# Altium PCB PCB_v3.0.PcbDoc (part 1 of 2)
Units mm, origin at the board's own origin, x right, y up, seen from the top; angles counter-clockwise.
Board outline 140 x 100 mm, 2 copper layers (Top Layer, Bottom Layer); 283 components, 163 nets, 757 pads, 121 vias.
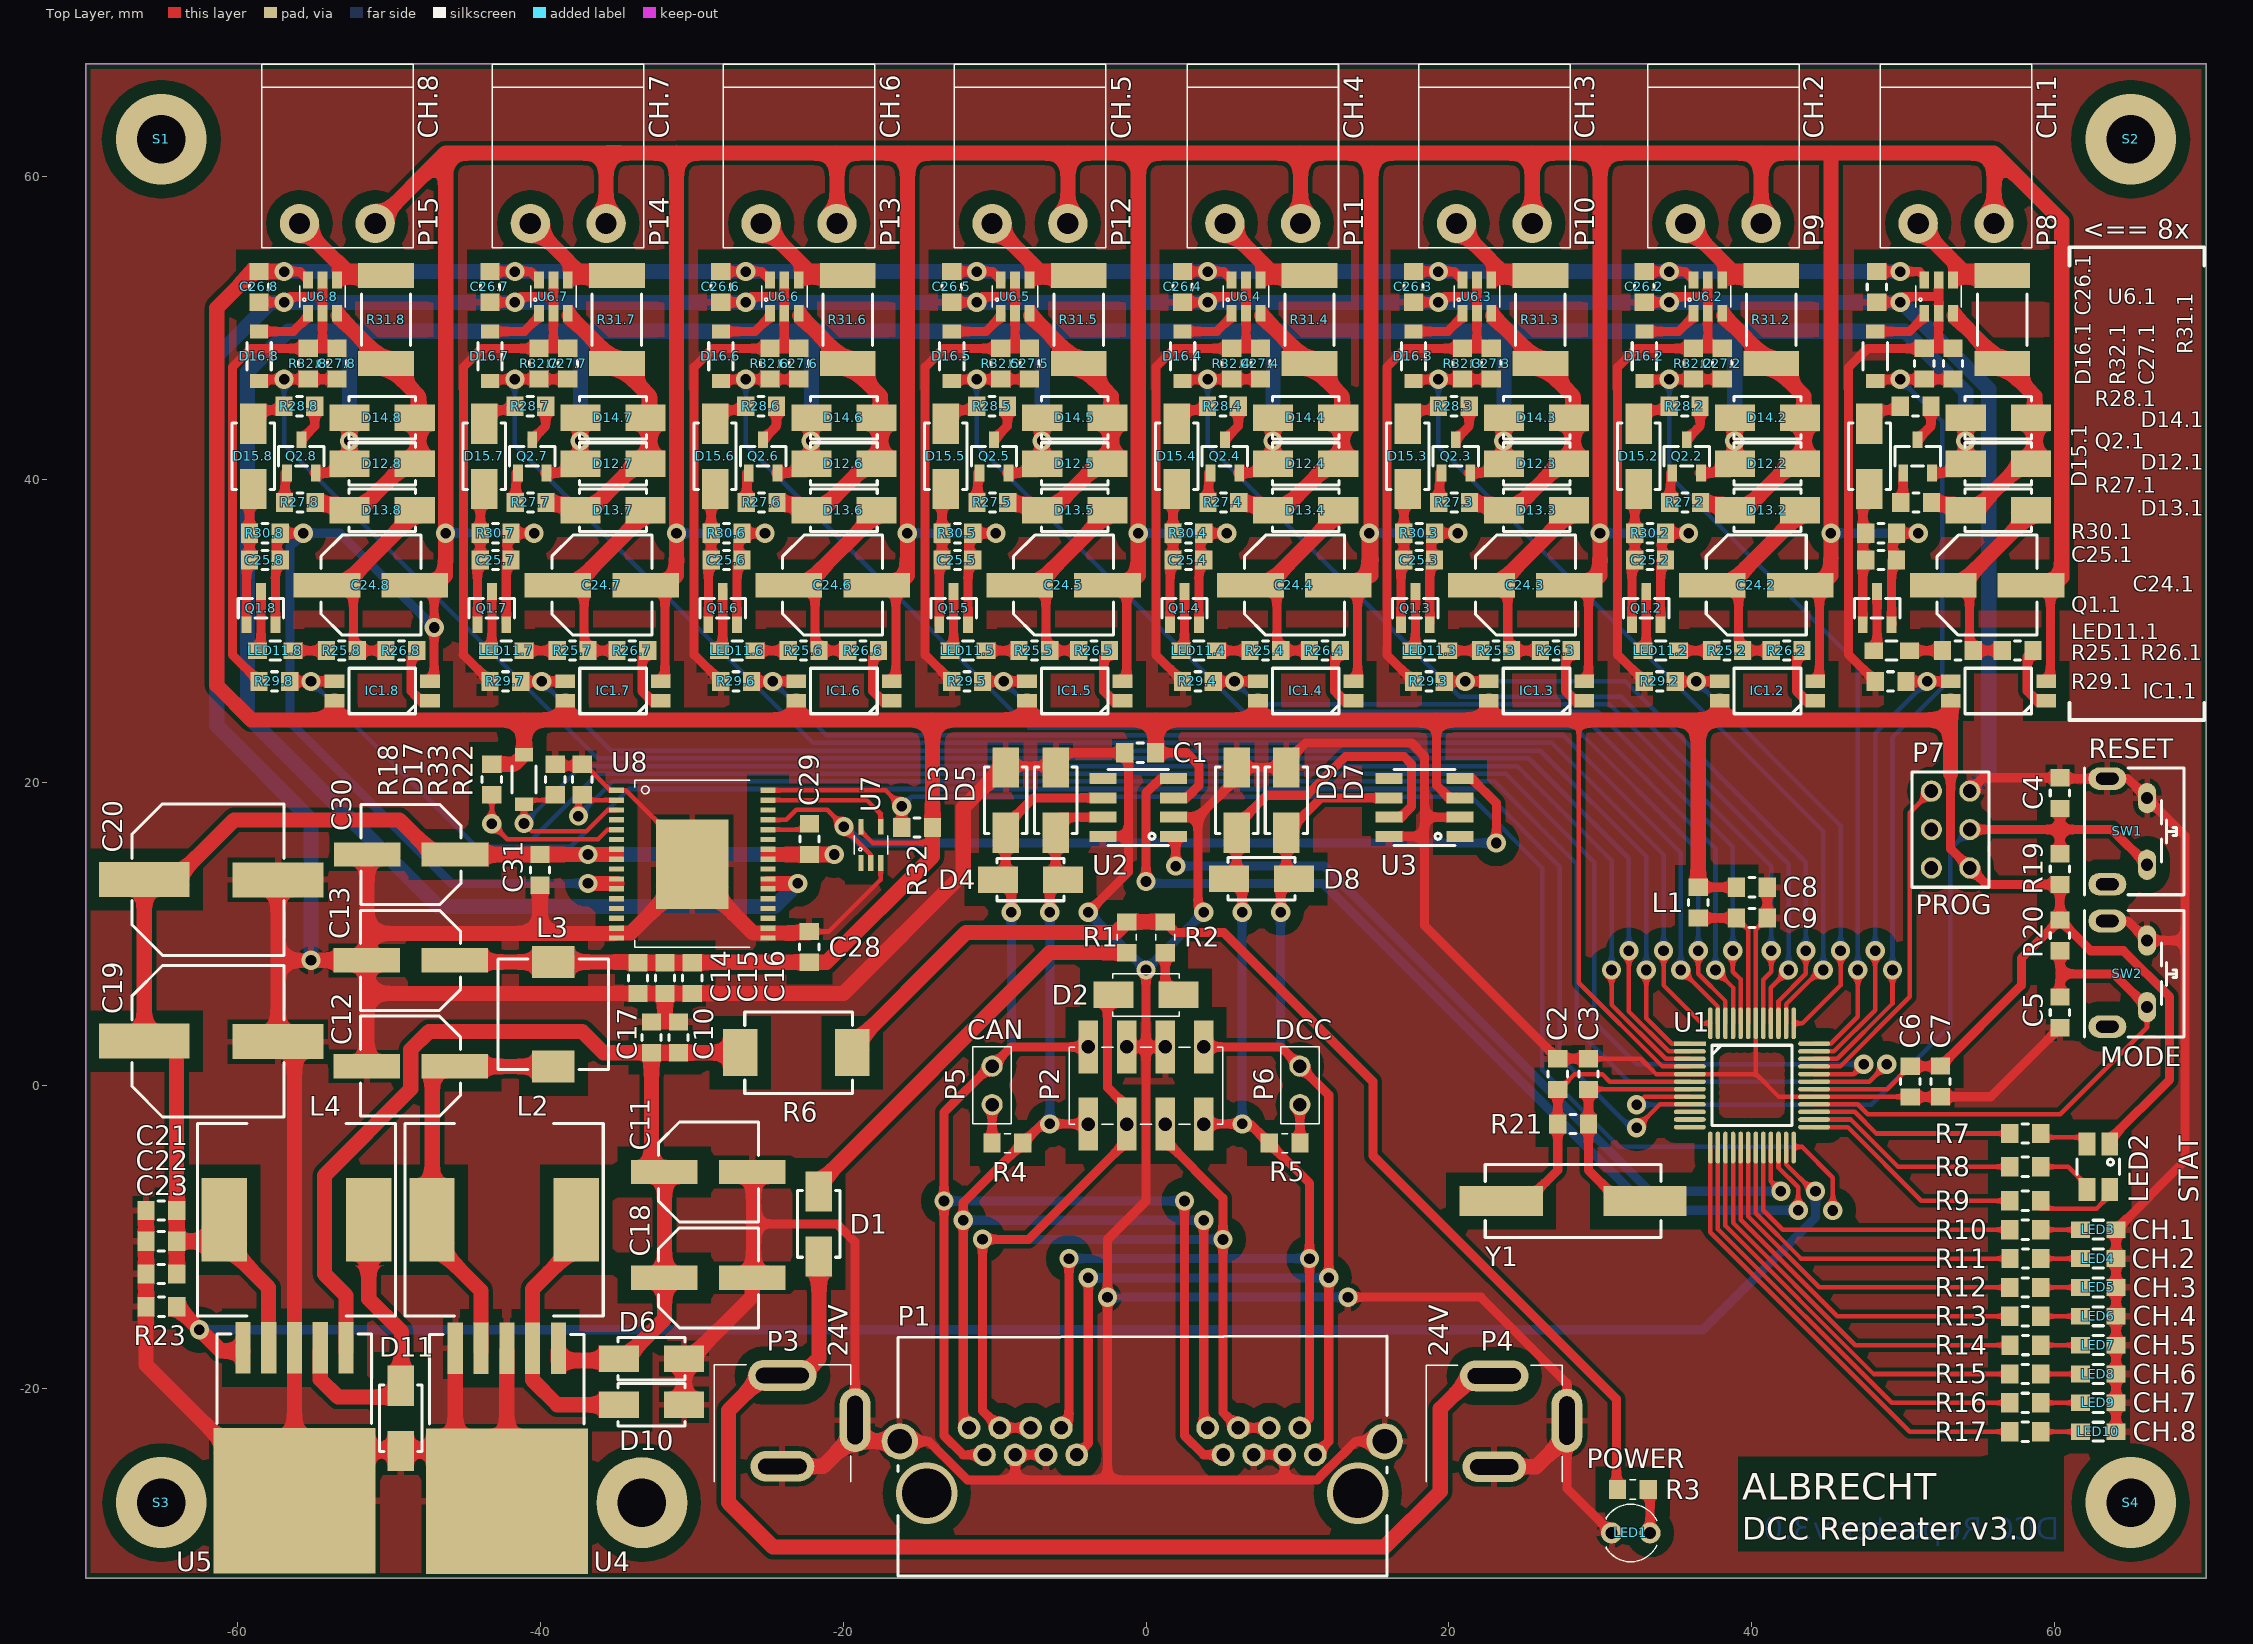
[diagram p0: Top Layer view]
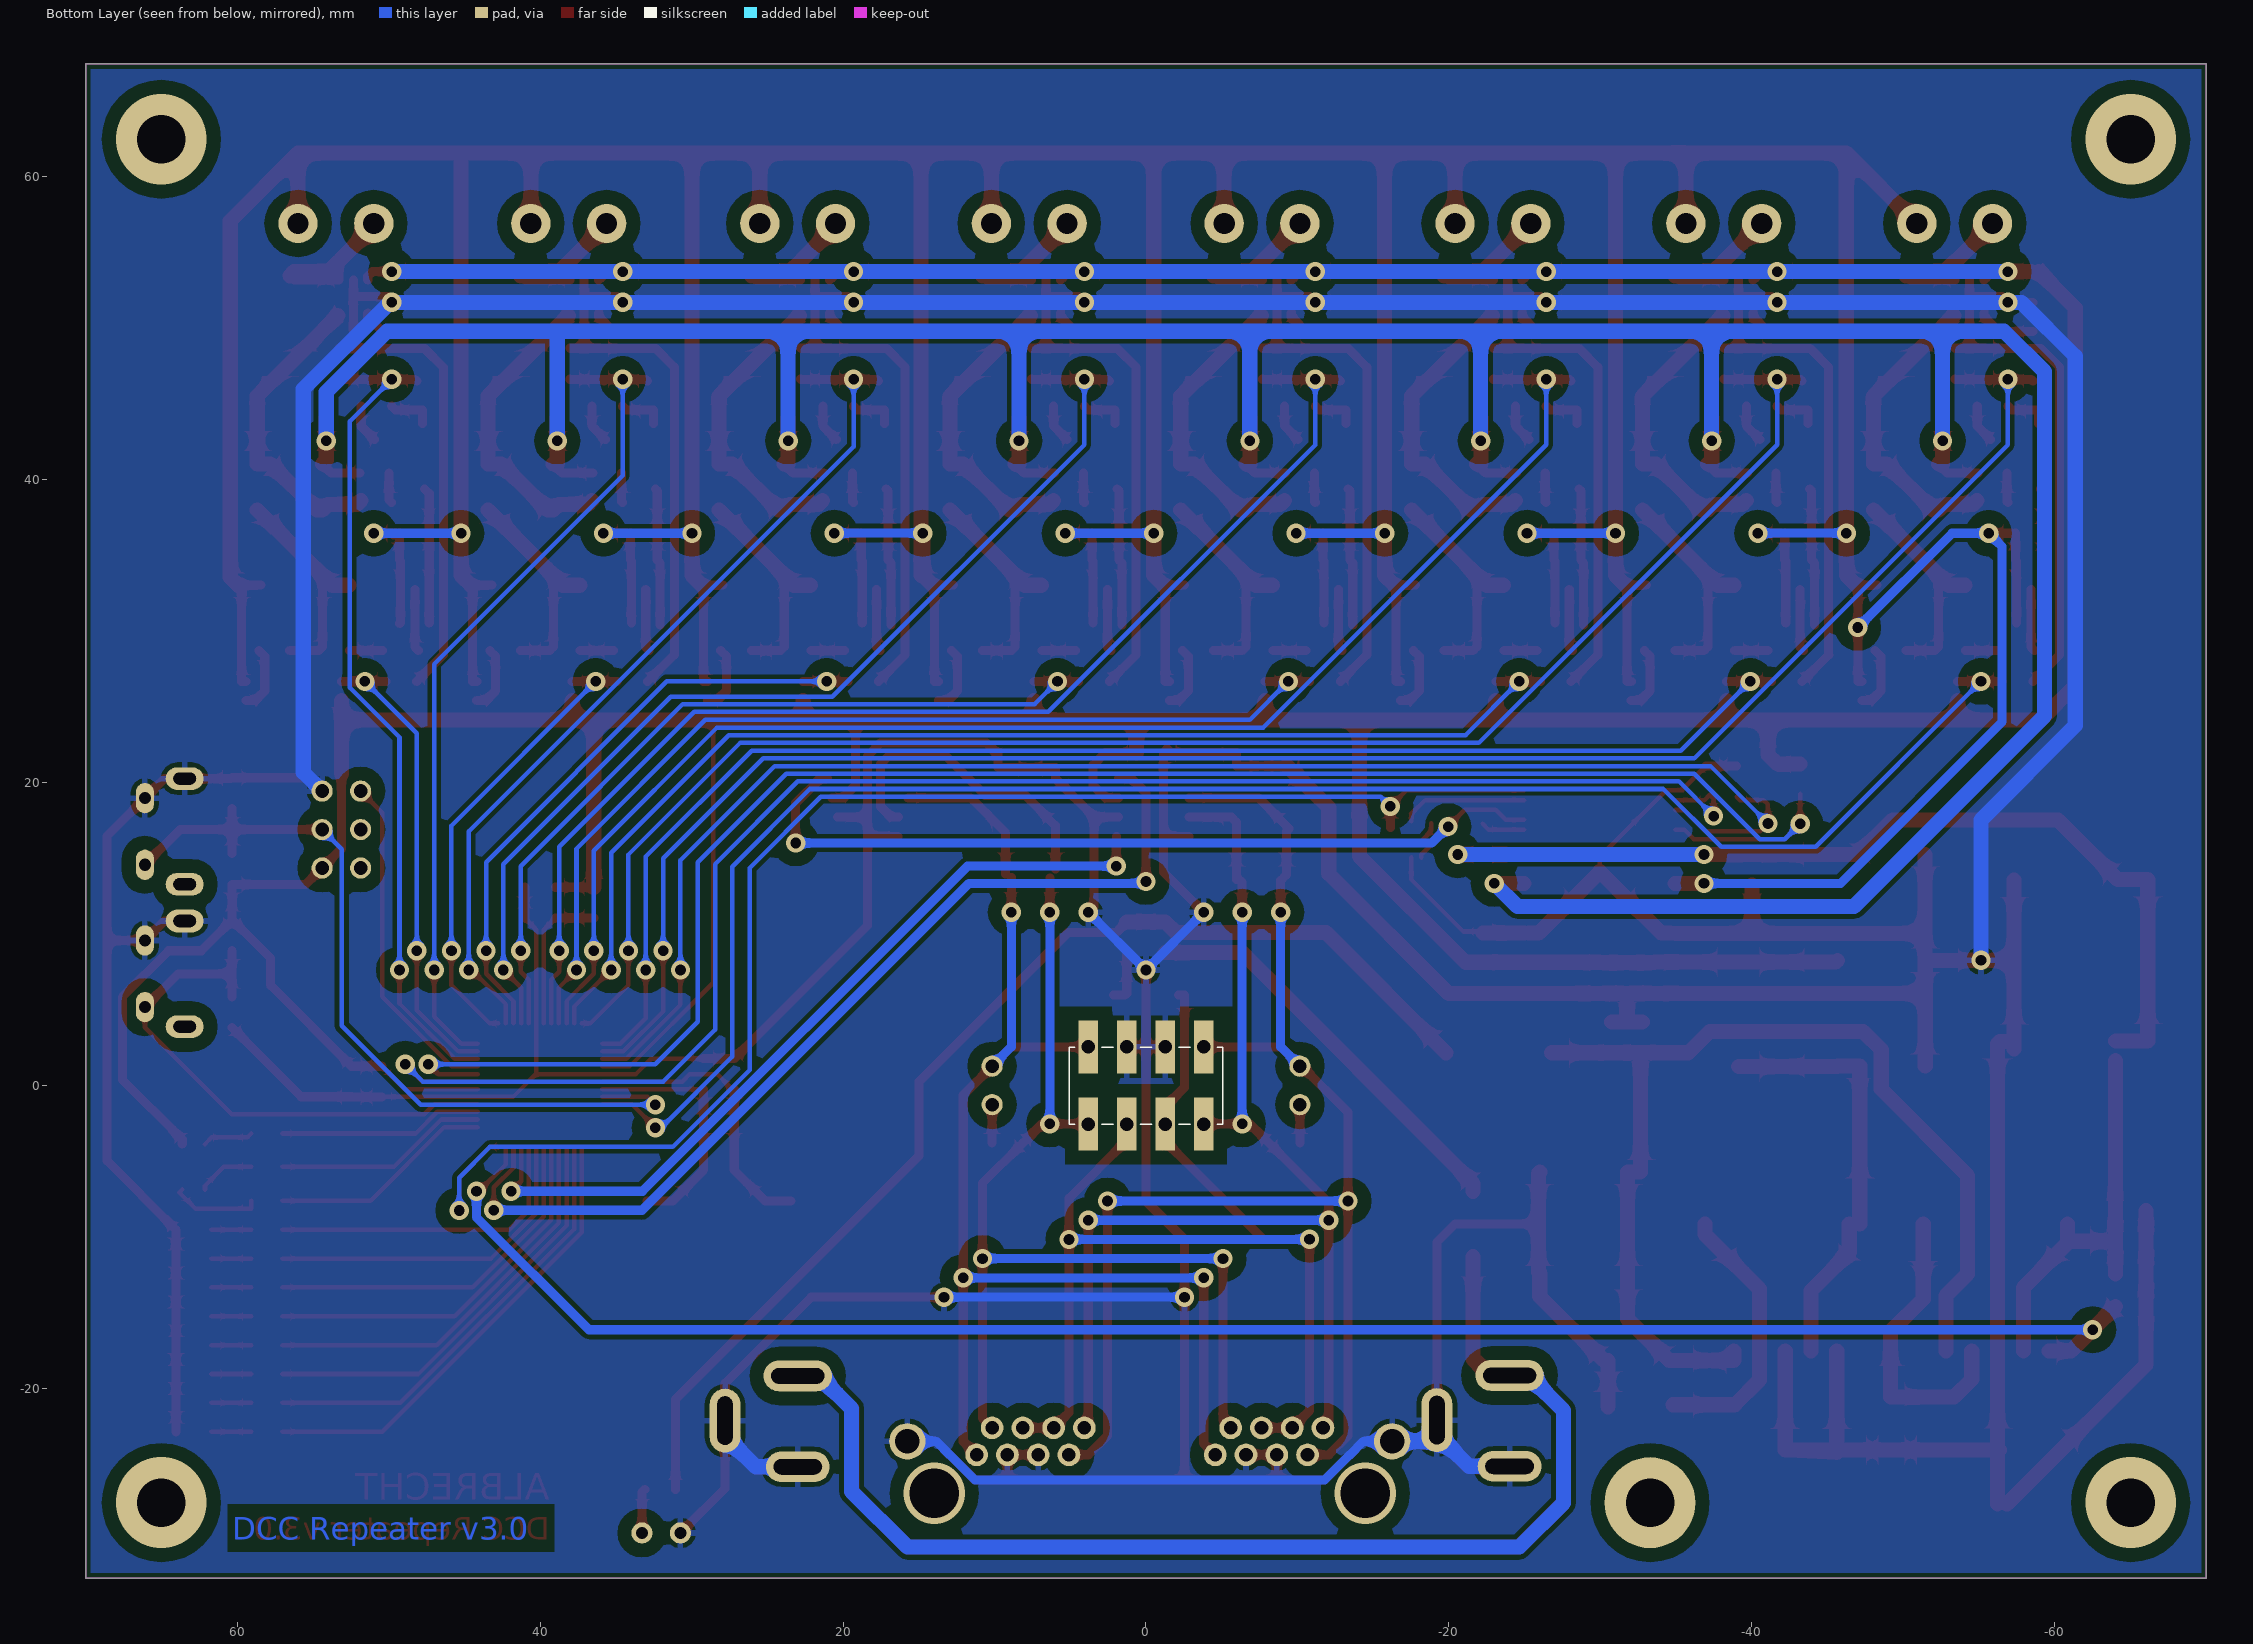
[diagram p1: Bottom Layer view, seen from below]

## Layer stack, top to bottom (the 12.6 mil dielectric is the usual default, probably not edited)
Top Solder: solder mask 0.0102, Solder Resist, Dk 3.5
Top Layer: signal copper 0.0356
Dielectric 1: dielectric 0.32, FR-4, Dk 4.8
Bottom Layer: signal copper 0.0356
Bottom Solder: solder mask 0.0102, Solder Resist, Dk 3.5

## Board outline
-70,-32.545 -70,67.455 70,67.455 70,-32.545

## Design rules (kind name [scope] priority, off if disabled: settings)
Clearance [All] p1: gap=0.2 ignorepadtopadclearanceinfootprint=FALSE except(0: Arc-Hole Track-Hole SMDPad-Hole THPad-Hole Via-Hole Fill-Hole Poly-Hole Region-Hole Text-Hole; 0.3: Arc-Poly Track-Poly Fill-Poly Poly-Poly Poly-Region Poly-Text; 0.9: SMDPad-Poly THPad-Poly Via-Poly)
Height [All] p1: minheight=0 maxheight=50 prefheight=10
HoleSize [All] p1: absolutevalues=TRUE maxlimit=3.6 minlimit=0.6 maxpercent=80.000 minpercent=20.000
MinimumSolderMaskSliver [All] p1: minsoldermaskwidth=0
PlaneConnect [All] p1: planeconnectstyle=Relief reliefexpansion=0.508 reliefentries=4 reliefconductorwidth=0.4 reliefairgap=0.3
PolygonConnect PolygonConnect_Vias [InNet('GND') and IsVia] p1: connectstyle=Relief reliefconductorwidth=0.4 reliefentries=4 polygonreliefangle="90 Angle" airgapwidth=0.3
PolygonConnect [All] p2: connectstyle=Relief reliefconductorwidth=0.4 reliefentries=4 polygonreliefangle="90 Angle" airgapwidth=0.3
RoomDefinition main_v3.0 [InComponentClass('main_v3.0')] p1: confinementstyle=ConfineIn formatcopy=TRUE lockcomponents=FALSE outline -69.977,-32.545 70.002,-32.545 70.002,67.691 -69.977,67.691
RoomDefinition U_Terminal_block [InComponentClass('U_Terminal_block')] p2: confinementstyle=ConfineIn formatcopy=TRUE lockcomponents=FALSE outline -60.96,54.61 60.96,54.61 60.96,67.455 -60.96,67.455
RoomDefinition U_Measure_current8 [InComponentClass('U_Measure_current8')] p3: confinementstyle=ConfineIn formatcopy=TRUE lockcomponents=FALSE outline -60.96,45.72 -45.72,45.72 -45.72,54.61 -60.96,54.61
RoomDefinition U_Measure_current7 [InComponentClass('U_Measure_current7')] p4: confinementstyle=ConfineIn formatcopy=TRUE lockcomponents=FALSE outline -45.72,45.72 -30.48,45.72 -30.48,54.61 -45.72,54.61
RoomDefinition U_Measure_current6 [InComponentClass('U_Measure_current6')] p5: confinementstyle=ConfineIn formatcopy=TRUE lockcomponents=FALSE outline -30.48,45.72 -15.24,45.72 -15.24,54.61 -30.48,54.61
RoomDefinition U_Measure_current5 [InComponentClass('U_Measure_current5')] p6: confinementstyle=ConfineIn formatcopy=TRUE lockcomponents=FALSE outline -15.24,45.72 0,45.72 0,54.61 -15.24,54.61
RoomDefinition U_Measure_current4 [InComponentClass('U_Measure_current4')] p7: confinementstyle=ConfineIn formatcopy=TRUE lockcomponents=FALSE outline 0,45.72 15.24,45.72 15.24,54.61 0,54.61
RoomDefinition U_Measure_current3 [InComponentClass('U_Measure_current3')] p8: confinementstyle=ConfineIn formatcopy=TRUE lockcomponents=FALSE outline 15.24,45.72 30.48,45.72 30.48,54.61 15.24,54.61
RoomDefinition U_Measure_current2 [InComponentClass('U_Measure_current2')] p9: confinementstyle=ConfineIn formatcopy=TRUE lockcomponents=FALSE outline 30.48,45.72 45.72,45.72 45.72,54.61 30.48,54.61
RoomDefinition U_Measure_current1 [InComponentClass('U_Measure_current1')] p10: confinementstyle=ConfineIn formatcopy=TRUE lockcomponents=FALSE outline 45.72,45.72 60.96,45.72 60.96,54.61 45.72,54.61
RoomDefinition U_Detect_current8 [InComponentClass('U_Detect_current8')] p11: confinementstyle=ConfineIn formatcopy=TRUE lockcomponents=FALSE outline -60.961,24.13 -45.72,24.13 -45.72,45.72 -60.961,45.72
RoomDefinition U_Detect_current7 [InComponentClass('U_Detect_current7')] p12: confinementstyle=ConfineIn formatcopy=TRUE lockcomponents=FALSE outline -45.722,24.13 -30.481,24.13 -30.481,45.72 -45.722,45.72
RoomDefinition U_Detect_current6 [InComponentClass('U_Detect_current6')] p13: confinementstyle=ConfineIn formatcopy=TRUE lockcomponents=FALSE outline -30.482,24.13 -15.241,24.13 -15.241,45.72 -30.482,45.72
RoomDefinition U_Detect_current5 [InComponentClass('U_Detect_current5')] p14: confinementstyle=ConfineIn formatcopy=TRUE lockcomponents=FALSE outline -15.241,24.13 0,24.13 0,45.72 -15.241,45.72
RoomDefinition U_Detect_current4 [InComponentClass('U_Detect_current4')] p15: confinementstyle=ConfineIn formatcopy=TRUE lockcomponents=FALSE outline 0,24.13 15.241,24.13 15.241,45.72 0,45.72
RoomDefinition U_Detect_current3 [InComponentClass('U_Detect_current3')] p16: confinementstyle=ConfineIn formatcopy=TRUE lockcomponents=FALSE outline 15.241,24.13 30.482,24.13 30.482,45.72 15.241,45.72
RoomDefinition U_Detect_current2 [InComponentClass('U_Detect_current2')] p17: confinementstyle=ConfineIn formatcopy=TRUE lockcomponents=FALSE outline 30.482,24.13 45.723,24.13 45.723,45.72 30.482,45.72
RoomDefinition U_Detect_current1 [InComponentClass('U_Detect_current1')] p18: confinementstyle=ConfineIn formatcopy=TRUE lockcomponents=FALSE outline 45.723,24.13 60.964,24.13 60.964,45.72 45.723,45.72
RoomDefinition U_DCC_Amplifier [InComponentClass('U_DCC_Amplifier')] p19: confinementstyle=ConfineIn formatcopy=TRUE lockcomponents=FALSE outline -54.482,6.985 -13.208,6.985 -13.208,22.86 -54.482,22.86
RoomDefinition U_connector [InComponentClass('U_connector')] p20: confinementstyle=ConfineIn formatcopy=TRUE lockcomponents=FALSE outline -34.29,-32.639 35,-32.639 35,12.827 -34.29,12.827
RoutingVias [All] p1: holewidth=0.7 width=1.27 viastyle="Through Hole" minholewidth=0.7 minwidth=1.27 maxholewidth=0.7 maxwidth=1.27
ShortCircuit ShortCircuit_Text [InPolygon vs IsText] p1: allowed=TRUE
ShortCircuit [All] p2: allowed=FALSE
SilkToSilkClearance [All] p1: silktosilkclearance=0.1
SilkToSolderMaskClearance [IsPad] p1: minsilkscreentomaskgap=0.1 clearancetoexposedcopper=TRUE
SolderMaskExpansion [All] p1: expansion=0.1
Width [All] p1: maxlimit=1 minlimit=0.3 preferedwidth=0.6
23 further rules are at their usual default settings.

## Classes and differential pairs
channel class measuring_v3.0: U_Measuring_1 U_Measuring_2 U_Measuring_3 U_Measuring_4 U_Measuring_5 U_Measuring_6 U_Measuring_7 U_Measuring_8
channel class measure_current_v3.0: U_Measure_current1 U_Measure_current2 U_Measure_current3 U_Measure_current4 U_Measure_current5 U_Measure_current6 U_Measure_current7 U_Measure_current8
channel class detect_current_v3.0: U_Detect_current1 U_Detect_current2 U_Detect_current3 U_Detect_current4 U_Detect_current5 U_Detect_current6 U_Detect_current7 U_Detect_current8
component class U_Terminal_block: P8 P9 P10 P11 P12 P13 P14 P15 P16
component class U_Measure_current8: C26.8 C27.8 D16.8 R31.8 R32.8 U6.8
component class U_Measure_current7: C26.7 C27.7 D16.7 R31.7 R32.7 U6.7
component class U_Measure_current6: C26.6 C27.6 D16.6 R31.6 R32.6 U6.6
component class U_Measure_current5: C26.5 C27.5 D16.5 R31.5 R32.5 U6.5
component class U_Measure_current4: C26.4 C27.4 D16.4 R31.4 R32.4 U6.4
component class U_Measure_current3: C26.3 C27.3 D16.3 R31.3 R32.3 U6.3
component class U_Measure_current2: C26.2 C27.2 D16.2 R31.2 R32.2 U6.2
component class U_Measure_current1: C26.1 C27.1 D16.1 R31.1 R32.1 U6.1
component class U_Detect_current8: C24.8 C25.8 D12.8 D13.8 D14.8 D15.8 IC1.8 LED11.8 Q1.8 Q2.8 R25.8 R26.8 R27.8 R28.8 R29.8 R30.8
component class U_Detect_current7: C24.7 C25.7 D12.7 D13.7 D14.7 D15.7 IC1.7 LED11.7 Q1.7 Q2.7 R25.7 R26.7 R27.7 R28.7 R29.7 R30.7
component class U_Detect_current6: C24.6 C25.6 D12.6 D13.6 D14.6 D15.6 IC1.6 LED11.6 Q1.6 Q2.6 R25.6 R26.6 R27.6 R28.6 R29.6 R30.6
component class U_Detect_current5: C24.5 C25.5 D12.5 D13.5 D14.5 D15.5 IC1.5 LED11.5 Q1.5 Q2.5 R25.5 R26.5 R27.5 R28.5 R29.5 R30.5
component class U_Detect_current4: C24.4 C25.4 D12.4 D13.4 D14.4 D15.4 IC1.4 LED11.4 Q1.4 Q2.4 R25.4 R26.4 R27.4 R28.4 R29.4 R30.4
component class U_Detect_current3: C24.3 C25.3 D12.3 D13.3 D14.3 D15.3 IC1.3 LED11.3 Q1.3 Q2.3 R25.3 R26.3 R27.3 R28.3 R29.3 R30.3
component class U_Detect_current2: C24.2 C25.2 D12.2 D13.2 D14.2 D15.2 IC1.2 LED11.2 Q1.2 Q2.2 R25.2 R26.2 R27.2 R28.2 R29.2 R30.2
component class U_Detect_current1: C24.1 C25.1 D12.1 D13.1 D14.1 D15.1 IC1.1 LED11.1 Q1.1 Q2.1 R25.1 R26.1 R27.1 R28.1 R29.1 R30.1
component class U_DCC_Amplifier: C28 C29 C30 C31 D17 R32 R33 R34 U7 U8
component class U_power: C10 C11 C12 C13 C14 C15 C16 C17 C18 C19 C20 C21 C22 C23 D6 D10 D11 L2 L3 L4 R6 R23 U4 U5
component class U_CAN: C1 D3 D4 D5 U2
component class U_MCU: C2 C3 C4 C5 C6 C7 C8 C9 D7 D8 D9 L1 LED2 LED3 LED4 LED5 LED6 LED7 LED8 LED9 LED10 P7 R7 R8 R9 R10 R11 R12 R13 R14 R15 R16 R17 R18 R19 R20 R21 R22 SW1 SW2 U1 U3 Y1
component class U_connector: D1 D2 LED1 P1 P2 P3 P4 P5 P6 R1 R2 R3 R4 R5
component class main_v3.0: S1 S2 S3 S4

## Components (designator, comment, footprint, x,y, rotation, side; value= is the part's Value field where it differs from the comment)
C1 "1u" SMD_CAPACITOR_0805 -0.381,21.96 r180 top
C2 "22p" SMD_CAPACITOR_0805 27.178,0.75 r270 top
C3 "22p" SMD_CAPACITOR_0805 29.21,0.75 r270 top
C4 "100n" SMD_CAPACITOR_0805 60.325,19.293 r90 top
C5 "100n" SMD_CAPACITOR_0805 60.325,4.826 r270 top
C6 "100n" SMD_CAPACITOR_0805 50.448,0.25 r270 top
C7 "100n" SMD_CAPACITOR_0805 52.451,0.265 r270 top
C8 "100n" SMD_CAPACITOR_0805 39.996,13.08 r0 top
C9 "330p" SMD_CAPACITOR_0805 39.996,11.05 r180 top
C10 "10u" SMD_CAPACITOR_0805 -30.861,3.175 r270 top value=100n
C11 "100u" SMD_CAPACITOR_D_6.3MM -28.891,-5.715 r90 top
C12 "100u" SMD_CAPACITOR_D_6.3MM -48.535,1.27 r270 top
C13 "100u" SMD_CAPACITOR_D_6.3MM -48.535,8.255 r270 top
C14 "10u" SMD_CAPACITOR_0805 -33.528,7.087 r90 top
C15 "100n" SMD_CAPACITOR_0805 -31.75,7.087 r90 top
C16 "10n" SMD_CAPACITOR_0805 -29.951,7.087 r90 top
C17 "10n" SMD_CAPACITOR_0805 -32.639,3.175 r270 top value=100n
C18 "100u" SMD_CAPACITOR_D_6.3MM -28.891,-12.7 r90 top
C19 "470u/16V" SMD_CAPACITOR_D_10MM -61.722,2.921 r90 top
C20 "470u/16V" SMD_CAPACITOR_D_10MM -61.722,13.589 r90 top
C21 "10u" SMD_CAPACITOR_0805 -65,-8.255 r0 top
C22 "100n" SMD_CAPACITOR_0805 -65,-10.287 r0 top
C23 "10n" SMD_CAPACITOR_0805 -65,-12.446 r0 top
C24.1 "10u/50V" SMD_CAPACITOR_D_6.3MM 55.523,33.02 r90 top (schematic designator C24)
C24.2 "10u/50V" SMD_CAPACITOR_D_6.3MM 40.282,33.02 r90 top (schematic designator C24)
C24.3 "10u/50V" SMD_CAPACITOR_D_6.3MM 25.041,33.02 r90 top (schematic designator C24)
C24.4 "10u/50V" SMD_CAPACITOR_D_6.3MM 9.8,33.02 r90 top (schematic designator C24)
C24.5 "10u/50V" SMD_CAPACITOR_D_6.3MM -5.441,33.02 r90 top (schematic designator C24)
C24.6 "10u/50V" SMD_CAPACITOR_D_6.3MM -20.682,33.02 r90 top (schematic designator C24)
C24.7 "10u/50V" SMD_CAPACITOR_D_6.3MM -35.922,33.02 r90 top (schematic designator C24)
C24.8 "10u/50V" SMD_CAPACITOR_D_6.3MM -51.161,33.02 r90 top (schematic designator C24)
C25.1 "100u" SMD_CAPACITOR_0805 48.518,34.68 r180 top (schematic designator C25)
C25.2 "100u" SMD_CAPACITOR_0805 33.277,34.68 r180 top (schematic designator C25)
C25.3 "100u" SMD_CAPACITOR_0805 18.036,34.68 r180 top (schematic designator C25)
C25.4 "100u" SMD_CAPACITOR_0805 2.795,34.68 r180 top (schematic designator C25)
C25.5 "100u" SMD_CAPACITOR_0805 -12.446,34.68 r180 top (schematic designator C25)
C25.6 "100u" SMD_CAPACITOR_0805 -27.687,34.68 r180 top (schematic designator C25)
C25.7 "100u" SMD_CAPACITOR_0805 -42.927,34.68 r180 top (schematic designator C25)
C25.8 "100u" SMD_CAPACITOR_0805 -58.166,34.68 r180 top (schematic designator C25)
C26.1 "100n" SMD_CAPACITOR_0805 48.244,52.705 r90 top (schematic designator C26)
C26.2 "100n" SMD_CAPACITOR_0805 32.893,52.705 r90 top (schematic designator C26)
C26.3 "100n" SMD_CAPACITOR_0805 17.653,52.705 r90 top (schematic designator C26)
C26.4 "100n" SMD_CAPACITOR_0805 2.413,52.705 r90 top (schematic designator C26)
C26.5 "100n" SMD_CAPACITOR_0805 -12.827,52.705 r90 top (schematic designator C26)
C26.6 "100n" SMD_CAPACITOR_0805 -28.067,52.705 r90 top (schematic designator C26)
C26.7 "100n" SMD_CAPACITOR_0805 -43.307,52.705 r90 top (schematic designator C26)
C26.8 "100n" SMD_CAPACITOR_0805 -58.547,52.705 r90 top (schematic designator C26)
C27.1 "1u" SMD_CAPACITOR_0805 53.274,47.646 r270 top (schematic designator C27)
C27.2 "1u" SMD_CAPACITOR_0805 38.034,47.646 r270 top (schematic designator C27)
C27.3 "1u" SMD_CAPACITOR_0805 22.794,47.646 r270 top (schematic designator C27)
C27.4 "1u" SMD_CAPACITOR_0805 7.554,47.646 r270 top (schematic designator C27)
C27.5 "1u" SMD_CAPACITOR_0805 -7.686,47.646 r270 top (schematic designator C27)
C27.6 "1u" SMD_CAPACITOR_0805 -22.926,47.646 r270 top (schematic designator C27)
C27.7 "1u" SMD_CAPACITOR_0805 -38.166,47.646 r270 top (schematic designator C27)
C27.8 "1u" SMD_CAPACITOR_0805 -53.406,47.646 r270 top (schematic designator C27)
C28 "100n" SMD_CAPACITOR_0805 -22.225,9.144 r270 top
C29 "100n" SMD_CAPACITOR_0805 -22.218,16.256 r90 top
C30 "100u" SMD_CAPACITOR_D_6.3MM -48.514,15.24 r270 top
C31 "100n" SMD_CAPACITOR_0805 -40.005,14.224 r90 top
D1 "B340A-E3/61T" SMD_DO-214AC -21.59,-9.144 r90 top
D2 "B340A-E3/61T" SMD_DO-214AC -0.002,5.969 r0 top
D3 "SMA6J5.0CA" SMD_DO-214AC -9.271,18.83 r90 top
D4 "SMA6J5.0CA" SMD_DO-214AC -7.622,13.589 r180 top
D5 "SMA6J5.0CA" SMD_DO-214AC -5.969,18.83 r270 top
D6 "SMA6J28CA" SMD_DO-214AC -32.641,-18.034 r180 top
D7 "SMA6J5.0CA" SMD_DO-214AC 9.271,18.83 r90 top
D8 "SMA6J5.0CA" SMD_DO-214AC 7.62,13.63 r0 top
D9 "SMA6J5.0CA" SMD_DO-214AC 5.978,18.83 r270 top
D10 "B340A-E3/61T" SMD_DO-214AC -32.639,-21.082 r180 top
D11 "B340A-E3/61T" SMD_DO-214AC -49.2,-21.971 r90 top
D12.1 "S1A+" SMD_DO-214AC 56.265,41.021 r180 top (schematic designator D12)
D12.2 "S1A+" SMD_DO-214AC 41.024,41.021 r180 top (schematic designator D12)
D12.3 "S1A+" SMD_DO-214AC 25.783,41.021 r180 top (schematic designator D12)
D12.4 "S1A+" SMD_DO-214AC 10.542,41.021 r180 top (schematic designator D12)
D12.5 "S1A+" SMD_DO-214AC -4.699,41.021 r180 top (schematic designator D12)
D12.6 "S1A+" SMD_DO-214AC -19.94,41.021 r180 top (schematic designator D12)
D12.7 "S1A+" SMD_DO-214AC -35.18,41.021 r180 top (schematic designator D12)
D12.8 "S1A+" SMD_DO-214AC -50.419,41.021 r180 top (schematic designator D12)
D13.1 "S1A+" SMD_DO-214AC 56.265,37.973 r0 top (schematic designator D13)
D13.2 "S1A+" SMD_DO-214AC 41.024,37.973 r0 top (schematic designator D13)
D13.3 "S1A+" SMD_DO-214AC 25.783,37.973 r0 top (schematic designator D13)
D13.4 "S1A+" SMD_DO-214AC 10.542,37.973 r0 top (schematic designator D13)
D13.5 "S1A+" SMD_DO-214AC -4.699,37.973 r0 top (schematic designator D13)
D13.6 "S1A+" SMD_DO-214AC -19.94,37.973 r0 top (schematic designator D13)
D13.7 "S1A+" SMD_DO-214AC -35.18,37.973 r0 top (schematic designator D13)
D13.8 "S1A+" SMD_DO-214AC -50.419,37.973 r0 top (schematic designator D13)
D14.1 "S1A+" SMD_DO-214AC 56.265,44.069 r0 top (schematic designator D14)
D14.2 "S1A+" SMD_DO-214AC 41.024,44.069 r0 top (schematic designator D14)
D14.3 "S1A+" SMD_DO-214AC 25.783,44.069 r0 top (schematic designator D14)
D14.4 "S1A+" SMD_DO-214AC 10.542,44.069 r0 top (schematic designator D14)
D14.5 "S1A+" SMD_DO-214AC -4.699,44.069 r0 top (schematic designator D14)
D14.6 "S1A+" SMD_DO-214AC -19.94,44.069 r0 top (schematic designator D14)
D14.7 "S1A+" SMD_DO-214AC -35.18,44.069 r0 top (schematic designator D14)
D14.8 "S1A+" SMD_DO-214AC -50.419,44.069 r0 top (schematic designator D14)
D15.1 "S1A+" SMD_DO-214AC 47.756,41.529 r270 top (schematic designator D15)
D15.2 "S1A+" SMD_DO-214AC 32.515,41.529 r270 top (schematic designator D15)
D15.3 "S1A+" SMD_DO-214AC 17.274,41.529 r270 top (schematic designator D15)
D15.4 "S1A+" SMD_DO-214AC 2.033,41.529 r270 top (schematic designator D15)
D15.5 "S1A+" SMD_DO-214AC -13.208,41.529 r270 top (schematic designator D15)
D15.6 "S1A+" SMD_DO-214AC -28.449,41.529 r270 top (schematic designator D15)
D15.7 "S1A+" SMD_DO-214AC -43.689,41.529 r270 top (schematic designator D15)
D15.8 "S1A+" SMD_DO-214AC -58.928,41.529 r270 top (schematic designator D15)
D16.1 "BAT46W-7-F" SMD_SOD-123 48.133,48.133 r270 top (schematic designator D16)
D16.2 "BAT46W-7-F" SMD_SOD-123 32.897,48.133 r270 top (schematic designator D16)
D16.3 "BAT46W-7-F" SMD_SOD-123 17.657,48.133 r270 top (schematic designator D16)
D16.4 "BAT46W-7-F" SMD_SOD-123 2.417,48.133 r270 top (schematic designator D16)
D16.5 "BAT46W-7-F" SMD_SOD-123 -12.823,48.133 r270 top (schematic designator D16)
D16.6 "BAT46W-7-F" SMD_SOD-123 -28.063,48.133 r270 top (schematic designator D16)
D16.7 "BAT46W-7-F" SMD_SOD-123 -43.303,48.133 r270 top (schematic designator D16)
D16.8 "BAT46W-7-F" SMD_SOD-123 -58.543,48.133 r270 top (schematic designator D16)
D17 "BAT46W-7-F" SMD_SOD-123 -41.056,20.193 r90 top
IC1.1 "TCMT1109" TCMT110x 56.265,26.035 r180 top (schematic designator IC1)
IC1.2 "TCMT1109" TCMT110x 41.024,26.035 r180 top (schematic designator IC1)
IC1.3 "TCMT1109" TCMT110x 25.783,26.035 r180 top (schematic designator IC1)
IC1.4 "TCMT1109" TCMT110x 10.542,26.035 r180 top (schematic designator IC1)
IC1.5 "TCMT1109" TCMT110x -4.699,26.035 r180 top (schematic designator IC1)
IC1.6 "TCMT1109" TCMT110x -19.94,26.035 r180 top (schematic designator IC1)
IC1.7 "TCMT1109" TCMT110x -35.18,26.035 r180 top (schematic designator IC1)
IC1.8 "TCMT1109" TCMT110x -50.419,26.035 r180 top (schematic designator IC1)
L1 "BLM21A102SPT" SMD_INDUCTOR_0805 36.449,12.065 r270 top
L2 "330u" SMD_INDUCTOR_12.5MM -42.367,-8.865 r270 top
L3 "20u" SMD_INDUCTOR_7.3MM -39.116,4.699 r90 top
L4 "100u" SMD_INDUCTOR_12.5MM -56.07,-8.865 r270 top
LED1 "Green" THT_LED_3MM 32,-29.545 r180 top
LED2 "ASMB-MTB0-0A3A2" SMD_LED_RGB 62.865,-5.37 r180 top
LED3 "Yellow" SMD_LED_0805 62.865,-9.525 r0 top
LED4 "Yellow" SMD_LED_0805 62.865,-11.43 r0 top
LED5 "Yellow" SMD_LED_0805 62.865,-13.335 r0 top
LED6 "Yellow" SMD_LED_0805 62.865,-15.24 r0 top
LED7 "Yellow" SMD_LED_0805 62.865,-17.145 r0 top
LED8 "Yellow" SMD_LED_0805 62.865,-19.05 r0 top
LED9 "Yellow" SMD_LED_0805 62.865,-20.955 r0 top
LED10 "Yellow" SMD_LED_0805 62.865,-22.86 r0 top
LED11.1 "Red" SMD_LED_0805 49.214,28.702 r180 top (schematic designator LED11)
LED11.2 "Red" SMD_LED_0805 33.973,28.702 r180 top (schematic designator LED11)
LED11.3 "Red" SMD_LED_0805 18.732,28.702 r180 top (schematic designator LED11)
LED11.4 "Red" SMD_LED_0805 3.491,28.702 r180 top (schematic designator LED11)
LED11.5 "Red" SMD_LED_0805 -11.75,28.702 r180 top (schematic designator LED11)
LED11.6 "Red" SMD_LED_0805 -26.991,28.702 r180 top (schematic designator LED11)
LED11.7 "Red" SMD_LED_0805 -42.231,28.702 r180 top (schematic designator LED11)
LED11.8 "Red" SMD_LED_0805 -57.47,28.702 r180 top (schematic designator LED11)
P1 "RJ45 2PORT" THT_RJ45_2PORT -16.377,-32.384 r0 top locked
P2 "Header 2x4" SMD_HEADER_100MIL_2X4_DOUBLESIDED 0,-0.01 r90 top locked
P3 "Power JACK 2.1/2.5" THT_POWER_JACK_2.1/2.5 -21.603,-22.146 r270 top locked
P4 "Power JACK 2.1/2.5" THT_POWER_JACK_2.1/2.5 25.387,-22.177 r270 top locked
P5 "Header 1x2" THT_HEADER_100MIL_1X2_MALE -10.16,0 r180 top locked
P6 "Header 1x2" THT_HEADER_100MIL_1X2_MALE 10.16,0 r180 top locked
P7 "Programming connector" THT_HEADER_100MIL_2X3_MALE 53.115,16.891 r180 top
P8 "End_Terminal_2pos_5.00mm" Terminal_Block_2pos_5.00mm_pitch 50.974,56.896 r0 top locked
P9 "End_Terminal_2pos_5.00mm" Terminal_Block_2pos_5.00mm_pitch 35.607,56.896 r0 top locked
P10 "End_Terminal_2pos_5.00mm" Terminal_Block_2pos_5.00mm_pitch 20.494,56.896 r0 top locked
P11 "End_Terminal_2pos_5.00mm" Terminal_Block_2pos_5.00mm_pitch 5.207,56.896 r0 top locked
P12 "End_Terminal_2pos_5.00mm" Terminal_Block_2pos_5.00mm_pitch -10.16,56.896 r0 top locked
P13 "End_Terminal_2pos_5.00mm" Terminal_Block_2pos_5.00mm_pitch -25.4,56.896 r0 top locked
P14 "End_Terminal_2pos_5.00mm" Terminal_Block_2pos_5.00mm_pitch -40.64,56.896 r0 top locked
P15 "End_Terminal_2pos_5.00mm" Terminal_Block_2pos_5.00mm_pitch -55.88,56.896 r0 top locked
Q1.1 "IRLML2030TRPBF" SMD_SOT-23 48.264,31.5 r0 top (schematic designator Q1)
Q1.2 "IRLML2030TRPBF" SMD_SOT-23 33.023,31.5 r0 top (schematic designator Q1)
Q1.3 "IRLML2030TRPBF" SMD_SOT-23 17.782,31.5 r0 top (schematic designator Q1)
Q1.4 "IRLML2030TRPBF" SMD_SOT-23 2.541,31.5 r0 top (schematic designator Q1)
Q1.5 "IRLML2030TRPBF" SMD_SOT-23 -12.7,31.5 r0 top (schematic designator Q1)
Q1.6 "IRLML2030TRPBF" SMD_SOT-23 -27.941,31.5 r0 top (schematic designator Q1)
Q1.7 "IRLML2030TRPBF" SMD_SOT-23 -43.181,31.5 r0 top (schematic designator Q1)
Q1.8 "IRLML2030TRPBF" SMD_SOT-23 -58.42,31.5 r0 top (schematic designator Q1)
Q2.1 "BC807" SMD_SOT-23 50.931,41.529 r0 top (schematic designator Q2)
Q2.2 "BC807" SMD_SOT-23 35.69,41.529 r0 top (schematic designator Q2)
Q2.3 "BC807" SMD_SOT-23 20.449,41.529 r0 top (schematic designator Q2)
Q2.4 "BC807" SMD_SOT-23 5.208,41.529 r0 top (schematic designator Q2)
Q2.5 "BC807" SMD_SOT-23 -10.033,41.529 r0 top (schematic designator Q2)
Q2.6 "BC807" SMD_SOT-23 -25.274,41.529 r0 top (schematic designator Q2)
Q2.7 "BC807" SMD_SOT-23 -40.514,41.529 r0 top (schematic designator Q2)
Q2.8 "BC807" SMD_SOT-23 -55.753,41.529 r0 top (schematic designator Q2)
R1 "0" SMD_RESISTOR_0805 -1.27,9.779 r270 top
R2 "0" SMD_RESISTOR_0805 1.27,9.779 r270 top
R3 "2k2" SMD_RESISTOR_0805 32.131,-26.67 r180 top
R4 "120" SMD_RESISTOR_0805 -9.144,-3.81 r0 top
R5 "120" SMD_RESISTOR_0805 9.148,-3.81 r180 top
R6 "MF-SM300-2" SMD_RESISTOR_PTC_MF-SM -23.086,2.16 r180 top
R7 "290" SMD_RESISTOR_0805 58.039,-3.175 r180 top
R8 "190" SMD_RESISTOR_0805 58.039,-5.37 r180 top
R9 "190" SMD_RESISTOR_0805 58.039,-7.62 r180 top
R10 "560" SMD_RESISTOR_0805 58.039,-9.525 r0 top
R11 "560" SMD_RESISTOR_0805 58.044,-11.43 r0 top
R12 "560" SMD_RESISTOR_0805 58.039,-13.335 r0 top
R13 "560" SMD_RESISTOR_0805 58.039,-15.24 r0 top
R14 "560" SMD_RESISTOR_0805 58.044,-17.145 r0 top
R15 "560" SMD_RESISTOR_0805 58.039,-19.05 r0 top
R16 "560" SMD_RESISTOR_0805 58.039,-20.955 r0 top
R17 "560" SMD_RESISTOR_0805 58.039,-22.86 r0 top
R18 "10k" SMD_RESISTOR_0805 -43.181,20.193 r90 top
R19 "10k" SMD_RESISTOR_0805 60.325,14.28 r270 top
R20 "10k" SMD_RESISTOR_0805 60.325,9.906 r90 top
R21 "1M" SMD_RESISTOR_0805 28.194,-2.54 r180 top
R22 "10k" SMD_RESISTOR_0805 -37.211,20.193 r270 top
R23 "10k" SMD_RESISTOR_0805 -65,-14.605 r0 top
R25.1 "560" SMD_RESISTOR_0805 53.598,28.702 r0 top (schematic designator R25)
R25.2 "560" SMD_RESISTOR_0805 38.357,28.702 r0 top (schematic designator R25)
R25.3 "560" SMD_RESISTOR_0805 23.116,28.702 r0 top (schematic designator R25)
R25.4 "560" SMD_RESISTOR_0805 7.875,28.702 r0 top (schematic designator R25)
R25.5 "560" SMD_RESISTOR_0805 -7.366,28.702 r0 top (schematic designator R25)
R25.6 "560" SMD_RESISTOR_0805 -22.607,28.702 r0 top (schematic designator R25)
R25.7 "560" SMD_RESISTOR_0805 -37.847,28.702 r0 top (schematic designator R25)
R25.8 "560" SMD_RESISTOR_0805 -53.086,28.702 r0 top (schematic designator R25)
R26.1 "330" SMD_RESISTOR_0805 57.535,28.702 r0 top (schematic designator R26)
R26.2 "330" SMD_RESISTOR_0805 42.294,28.702 r0 top (schematic designator R26)
R26.3 "330" SMD_RESISTOR_0805 27.053,28.702 r0 top (schematic designator R26)
R26.4 "330" SMD_RESISTOR_0805 11.812,28.702 r0 top (schematic designator R26)
R26.5 "330" SMD_RESISTOR_0805 -3.429,28.702 r0 top (schematic designator R26)
R26.6 "330" SMD_RESISTOR_0805 -18.67,28.702 r0 top (schematic designator R26)
R26.7 "330" SMD_RESISTOR_0805 -33.91,28.702 r0 top (schematic designator R26)
R26.8 "330" SMD_RESISTOR_0805 -49.149,28.702 r0 top (schematic designator R26)
R27.1 "1k" SMD_RESISTOR_0805 50.828,38.481 r0 top (schematic designator R27)
R27.2 "1k" SMD_RESISTOR_0805 35.587,38.481 r0 top (schematic designator R27)
R27.3 "1k" SMD_RESISTOR_0805 20.346,38.481 r0 top (schematic designator R27)
R27.4 "1k" SMD_RESISTOR_0805 5.105,38.481 r0 top (schematic designator R27)
R27.5 "1k" SMD_RESISTOR_0805 -10.136,38.481 r0 top (schematic designator R27)
R27.6 "1k" SMD_RESISTOR_0805 -25.377,38.481 r0 top (schematic designator R27)
R27.7 "1k" SMD_RESISTOR_0805 -40.617,38.481 r0 top (schematic designator R27)
R27.8 "1k" SMD_RESISTOR_0805 -55.856,38.481 r0 top (schematic designator R27)
R28.1 "1k" SMD_RESISTOR_0805 50.8,44.831 r0 top (schematic designator R28)
R28.2 "1k" SMD_RESISTOR_0805 35.56,44.831 r0 top (schematic designator R28)
R28.3 "1k" SMD_RESISTOR_0805 20.319,44.831 r0 top (schematic designator R28)
R28.4 "1k" SMD_RESISTOR_0805 5.078,44.831 r0 top (schematic designator R28)
R28.5 "1k" SMD_RESISTOR_0805 -10.163,44.831 r0 top (schematic designator R28)
R28.6 "1k" SMD_RESISTOR_0805 -25.404,44.831 r0 top (schematic designator R28)
R28.7 "1k" SMD_RESISTOR_0805 -40.644,44.831 r0 top (schematic designator R28)
R28.8 "1k" SMD_RESISTOR_0805 -55.883,44.831 r0 top (schematic designator R28)
R29.1 "10k" SMD_RESISTOR_0805 49.153,26.67 r0 top (schematic designator R29)
R29.2 "10k" SMD_RESISTOR_0805 33.912,26.67 r0 top (schematic designator R29)
R29.3 "10k" SMD_RESISTOR_0805 18.671,26.67 r0 top (schematic designator R29)
R29.4 "10k" SMD_RESISTOR_0805 3.43,26.67 r0 top (schematic designator R29)
R29.5 "10k" SMD_RESISTOR_0805 -11.811,26.67 r0 top (schematic designator R29)
R29.6 "10k" SMD_RESISTOR_0805 -27.052,26.67 r0 top (schematic designator R29)
R29.7 "10k" SMD_RESISTOR_0805 -42.292,26.67 r0 top (schematic designator R29)
R29.8 "10k" SMD_RESISTOR_0805 -57.531,26.67 r0 top (schematic designator R29)
R30.1 "1M" SMD_RESISTOR_0805 48.518,36.449 r180 top (schematic designator R30)
R30.2 "1M" SMD_RESISTOR_0805 33.277,36.449 r180 top (schematic designator R30)
R30.3 "1M" SMD_RESISTOR_0805 18.036,36.449 r180 top (schematic designator R30)
R30.4 "1M" SMD_RESISTOR_0805 2.795,36.449 r180 top (schematic designator R30)
R30.5 "1M" SMD_RESISTOR_0805 -12.446,36.449 r180 top (schematic designator R30)
R30.6 "1M" SMD_RESISTOR_0805 -27.687,36.449 r180 top (schematic designator R30)
R30.7 "1M" SMD_RESISTOR_0805 -42.927,36.449 r180 top (schematic designator R30)
R30.8 "1M" SMD_RESISTOR_0805 -58.166,36.449 r180 top (schematic designator R30)
R31.1 "100m" Resistor 56.515,50.546 r90 top (schematic designator R31)
R31.2 "100m" Resistor 41.275,50.546 r90 top (schematic designator R31)
R31.3 "100m" Resistor 26.035,50.546 r90 top (schematic designator R31)
R31.4 "100m" Resistor 10.795,50.546 r90 top (schematic designator R31)
R31.5 "100m" Resistor -4.445,50.546 r90 top (schematic designator R31)
R31.6 "100m" Resistor -19.685,50.546 r90 top (schematic designator R31)
R31.7 "100m" Resistor -34.925,50.546 r90 top (schematic designator R31)
R31.8 "100m" Resistor -50.165,50.546 r90 top (schematic designator R31)
R32 "10k" SMD_RESISTOR_0805 -15.113,17.018 r0 top
R32.1 "20k" SMD_RESISTOR_0805 51.374,47.646 r270 top (schematic designator R32)
R32.2 "20k" SMD_RESISTOR_0805 36.134,47.646 r270 top (schematic designator R32)
R32.3 "20k" SMD_RESISTOR_0805 20.894,47.646 r270 top (schematic designator R32)
R32.4 "20k" SMD_RESISTOR_0805 5.654,47.646 r270 top (schematic designator R32)
R32.5 "20k" SMD_RESISTOR_0805 -9.586,47.646 r270 top (schematic designator R32)
R32.6 "20k" SMD_RESISTOR_0805 -24.826,47.646 r270 top (schematic designator R32)
R32.7 "20k" SMD_RESISTOR_0805 -40.066,47.646 r270 top (schematic designator R32)
R32.8 "20k" SMD_RESISTOR_0805 -55.306,47.646 r270 top (schematic designator R32)
R33 "300" SMD_RESISTOR_0805 -38.989,20.193 r270 top
S1 "Hex Spacer M3" THT_HEX_SPACER_M3L20 -65,62.455 r0 top locked
S2 "Hex Spacer M3" THT_HEX_SPACER_M3L20 65,62.455 r0 top locked
S3 "Hex Spacer M3" THT_HEX_SPACER_M3L20 -65,-27.545 r0 top locked
S4 "Hex Spacer M3" THT_HEX_SPACER_M3L20 65,-27.545 r0 top locked
SW1 "Switch" THT_SWITCH_SPST_90 64.77,16.764 r270 top
SW2 "Switch" THT_SWITCH_SPST_90 64.77,7.366 r270 top
U1 "MC9S08DZ128MLF" SMD_LQFP-48 40,0 r0 top locked
U2 "MCP2551" SMD_SOIC-8 -0.511,18.346 r180 top
U3 "MCP2551-I/SN" SMD_SOIC-8 18.38,18.346 r180 top
U4 "TL2575-05" SMD_TO-263-5 -42.191,-17.348 r180 top
U5 "LM2576D2T-15G" SMD_TO-263-5 -56.21,-17.323 r180 top
U6.1 "INA181" SMD_SOT-23-6 52.324,52.07 r0 top value=INA181A3 (schematic designator U6)
U6.2 "INA181" SMD_SOT-23-6 37.084,52.07 r0 top value=INA181A3 (schematic designator U6)
U6.3 "INA181" SMD_SOT-23-6 21.844,52.07 r0 top value=INA181A3 (schematic designator U6)
U6.4 "INA181" SMD_SOT-23-6 6.604,52.07 r0 top value=INA181A3 (schematic designator U6)
U6.5 "INA181" SMD_SOT-23-6 -8.636,52.07 r0 top value=INA181A3 (schematic designator U6)
U6.6 "INA181" SMD_SOT-23-6 -23.876,52.07 r0 top value=INA181A3 (schematic designator U6)
U6.7 "INA181" SMD_SOT-23-6 -39.116,52.07 r0 top value=INA181A3 (schematic designator U6)
U6.8 "INA181" SMD_SOT-23-6 -54.356,52.07 r0 top value=INA181A3 (schematic designator U6)
U7 "SN74LVC1G14DCKR" SMD_SC-70-5 -18.161,15.875 r90 top
U8 "MC34931EK" SMD_WSOIC32 -29.951,14.605 r0 top
Y1 "8MHz" SMD_XTAL_HC-49 28.194,-7.63 r180 top

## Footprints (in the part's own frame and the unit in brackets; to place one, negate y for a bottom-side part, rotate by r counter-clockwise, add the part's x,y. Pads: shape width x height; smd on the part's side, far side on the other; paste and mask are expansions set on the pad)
Resistor [mm] "Resistor_2512"
  rect 1.65x3.68 smd: 1(-2.9,0) 2(2.9,0)
  silkscreen extent -1.7,-1.63 1.7,1.63, body extent -3.17,-1.63 3.18,1.63, height 0.58
SMD_CAPACITOR_0805 [mm]
  rect 1.14x1.27 smd: 1(-1.015,0) 2(1.015,0)
  silkscreen extent -0.2,-0.64 0.2,0.64, body extent -1,-0.6 1,0.6, height 1.18
SMD_CAPACITOR_D_6.3MM [mm]
  rect 1.6x4.4 smd: 1(0,2.9) 2(0,-2.9)
  silkscreen extent -3.3,-3.3 3.3,3.3, body extent -3.3,-3.5 3.3,3.5, height 7.71
SMD_CAPACITOR_D_10MM [mm]
  rect 2.3x6 smd: 1(0,4.4) 2(-0.025,-4.425)
  silkscreen extent -5,-4.83 5,5.2, body extent -5,-4.85 5,5.15, height 10.5
SMD_DO-214AC [mm]
  rect 2.65x1.75 smd: 1(-2.15,0) 2(2.15,0)
  silkscreen extent -2.2,-1.4 2.2,1.4, body extent -2.5,-1.35 2.5,1.35, height 2.19
SMD_HEADER_100MIL_2X4_DOUBLESIDED [mm]
  rect 3.5x1.27 hole 0.9 mask+0.05: 1(-2.55,3.81) 2(2.55,3.81) 3(-2.55,1.27) 4(2.55,1.27) 5(-2.55,-1.27) 6(2.55,-1.27) 7(-2.55,-3.81) 8(2.55,-3.81)
  silkscreen extent -2.54,-5.08 2.54,5.08, body extent -3.75,-5.08 3.75,5.08, height 9.57
SMD_INDUCTOR_7.3MM [mm]
  rect 2.1x2.8 smd: 1(-3.45,0) 2(3.45,0)
  silkscreen extent -3.65,-3.65 3.65,3.65, body extent -3.65,-3.65 3.65,3.65, height 4
SMD_INDUCTOR_12.5MM [mil]
  rect 217x118 smd: 1(0,187.5) 2(0,-187.5)
  silkscreen extent -250,-257 250,258, body extent -242,-242 242,242, height 402
SMD_INDUCTOR_0805 [mm]
  rect 1.14x1.27 smd: 1(-1.015,0) 2(1.015,0)
  silkscreen extent -0.2,-0.64 0.2,0.64, body extent -1,-0.62 1,0.63, height 1.25
SMD_LED_0805 [mm]
  rect 1.25x1.1 smd mask+0.1: 1(-1.175,0) 2(1.175,0)
  silkscreen extent -0.35,-0.63 0.35,0.63, body extent -1,-0.62 1,0.62, height 1.1
SMD_LED_RGB [mm]
  rect 1.1x1.5 smd: 1(-0.75,-1.5) 2(-0.75,1.5) 3(0.75,1.5) 4(0.75,-1.5)
  silkscreen extent -1.4,-0.5 1.4,0.5, body extent -1.4,-1.6 1.4,1.6, height 1.91
SMD_LQFP-48 [mm]
  rect 2.1x0.3 smd: 1(-4.1,2.75)
  oval 2.1x0.3 smd: 2(-4.1,2.25) 3(-4.1,1.75) 4(-4.1,1.25) 5(-4.1,0.75) 6(-4.1,0.25) 7(-4.1,-0.25) 8(-4.1,-0.75) 9(-4.1,-1.25) 10(-4.1,-1.75) 11(-4.1,-2.25) 12(-4.1,-2.75) 25(4.1,-2.75) 26(4.1,-2.25) 27(4.1,-1.75) 28(4.1,-1.25) 29(4.1,-0.75) 30(4.1,-0.25) 31(4.1,0.25) 32(4.1,0.75) 33(4.1,1.25) 34(4.1,1.75) 35(4.1,2.25) 36(4.1,2.75)
  oval 0.3x2.1 smd: 13(-2.75,-4.1) 14(-2.25,-4.1) 15(-1.75,-4.1) 16(-1.25,-4.1) 17(-0.75,-4.1) 18(-0.25,-4.1) 19(0.25,-4.1) 20(0.75,-4.1) 21(1.25,-4.1) 22(1.75,-4.1) 23(2.25,-4.1) 24(2.75,-4.1) 37(2.75,4.1) 38(2.25,4.1) 39(1.75,4.1) 40(1.25,4.1) 41(0.75,4.1) 42(0.25,4.1) 43(-0.25,4.1) 44(-0.75,4.1) 45(-1.25,4.1) 46(-1.75,4.1) 47(-2.25,4.1) 48(-2.75,4.1)
  silkscreen extent -2.65,-2.65 2.65,2.65, body extent -4.51,-4.51 4.51,4.51, height 1.1
SMD_RESISTOR_0805 [mm]
  rect 1.14x1.27 smd: 1(-1.015,0) 2(1.015,0)
  silkscreen extent -0.2,-0.64 0.2,0.64, body extent -1.02,-0.64 1.03,0.64, height 0.61
SMD_RESISTOR_PTC_MF-SM [mm]
  rect 2.3x3.1 smd: 1(-3.7,0) 2(3.7,0)
  silkscreen extent -3.7,-2.7 3.4,2.7, body extent -3.68,-2.72 3.68,2.72, height 3.18
SMD_SC-70-5 [mm]
  rect 1.05x0.35 smd: 1(-1.2,0.65) 2(-1.2,0) 3(-1.2,-0.65) 4(1.2,-0.65) 5(1.2,0.65)
  silkscreen extent -0.6,-1.1 0.6,1.1, body extent -1.15,-1.05 1.15,1.05, height 1
SMD_SOD-123 [mm]
  rect 0.91x1.2 smd: 1(-1.635,0) 2(1.635,0)
  silkscreen extent -0.9,-0.8 0.9,0.8, body extent -1.65,-0.8 1.65,0.8, height 1.2
SMD_SOIC-8 [mm]
  rect 1.78x0.72 smd: 1(-2.34,1.905) 2(-2.34,0.635) 3(-2.34,-0.635) 4(-2.34,-1.905) 5(2.34,-1.905) 6(2.34,-0.635) 7(2.34,0.635) 8(2.34,1.905)
  silkscreen extent -2,-2.5 2,2.5, body extent -3,-2.45 3,2.45, height 1.75
SMD_SOT-23 [mm]
  rect 0.65x1.1 smd: 1(-0.95,-1.1) 2(0.95,-1.1) 3(0,1.1)
  silkscreen extent -1.5,-0.65 1.5,0.65, body extent -1.5,-1.13 1.5,1.13, height 1.22
SMD_SOT-23-6 [mm]
  rect 0.65x1.1 smd: 1(-0.95,-1.1) 2(0,-1.1) 3(0.95,-1.1) 4(0.95,1.1) 5(0,1.1) 6(-0.95,1.1)
  silkscreen extent -1.5,-0.7 1.5,0.7, body extent -1.55,-0.75 1.55,0.75, height 1
SMD_TO-263-5 [mm]
  rect 1x3.4 smd mask+0.05: 1(-3.4,0) 2(-1.7,0) 3(0,0) 4(1.7,0) 5(3.4,0)
  rect 10.7x9.6 smd mask+0.05: 3(0,10.1)
  silkscreen extent -5.1,-0.9 5.1,5, body extent -5.08,-0.87 5.08,13.77, height 4.57
SMD_WSOIC32 [mm]
  rect 1x0.35 smd mask+0.05: 1(-5,4.875) 2(-5,4.225) 3(-5,3.575) 4(-5,2.925) 5(-5,2.275) 6(-5,1.625) 7(-5,0.975) 8(-5,0.325) 9(-5,-0.325) 10(-5,-0.975) 11(-5,-1.625) 12(-5,-2.275) 13(-5,-2.925) 14(-5,-3.575) 15(-5,-4.225) 16(-5,-4.875) 17(5,-4.875) 18(5,-4.225) 19(5,-3.575) 20(5,-2.925) 21(5,-2.275) 22(5,-1.625) 23(5,-0.975) 24(5,-0.325) 25(5,0.325) 26(5,0.975) 27(5,1.625) 28(5,2.275) 29(5,2.925) 30(5,3.575) 31(5,4.225) 32(5,4.875)
  rect 4.8x5.9 smd mask+0.05: 33(0,0)
  silkscreen extent -3.8,-5.48 3.8,5.53, body extent -3.85,-5.53 3.85,5.58, height 2.45
SMD_XTAL_HC-49 [mm]
  rect 5.5x2 smd: 1(-4.75,0)
  rect 5.5x2 smd mask+0.1: 2(4.75,0)
  silkscreen extent -5.8,-2.4 5.8,2.4, body extent -6.4,-2.41 6.4,2.42, height 4.3
TCMT110x [mm] "optoèlen"
  rect 1.3x0.9 smd: 1(-3.15,0.635) 2(-3.15,-0.635) 3(3.15,-0.635) 4(3.15,0.635)
  silkscreen extent -2.2,-1.5 2.2,1.5, body extent -2.3,-1.6 2.3,1.6, height 2
Terminal_Block_2pos_5.00mm_pitch [mm]
  round 2.6 hole 1.4: 1(0,0) 2(5,0)
  silkscreen extent -2.5,-1.6 7.5,10.5, body extent -2.5,-2 7.5,10, height 8.6
THT_HEADER_100MIL_1X2_MALE [mm]
  round 1.4 hole 0.9: 1(0,1.27) 2(0,-1.27)
  silkscreen extent -1.27,-2.54 1.27,2.54, body extent -1.27,-2.54 1.27,2.54, height 8.54
THT_HEADER_100MIL_2X3_MALE [mm]
  round 1.4 hole 0.9: 1(-1.27,2.54) 2(1.27,2.54) 3(-1.27,0) 4(1.27,0) 5(-1.27,-2.54) 6(1.27,-2.54)
  silkscreen extent -2.54,-3.81 2.54,3.81, body extent -2.54,-3.81 2.54,3.81, height 8.54
THT_HEX_SPACER_M3L20 [mm]
  body extent -2.5,-2.89 2.5,2.89, height 5.58
THT_LED_3MM [mm]
  round 1.4 hole 0.8: 1(-1.27,0) 2(1.27,0)
  silkscreen extent -1.72,-1.9 1.61,1.9, body extent -1.9,-1.9 1.6,1.9, height 5.6
THT_POWER_JACK_2.1/2.5 [mil]
  oval 80x178 hole 40 slot 138 at 90 deg: 1(-118.11,-94.49)
  oval 166x80 hole 40 slot 126 at 0 deg: 2(-1.97,94.49)
  oval 80x166 hole 40 slot 126 at 90 deg: 3(118.11,-94.49)
  silkscreen extent -146,-272 157,83, body extent -144,-272 407,98, height 433
THT_RJ45_2PORT [mm]
  round 2.4 hole 1.6: 0(0.13,8.89) 0(32.13,8.89)
  round 1.5 hole 0.9: 1(4.695,9.78) 2(5.715,8) 3(6.725,9.78) 4(7.745,8) 5(8.755,9.78) 6(9.775,8) 7(10.785,9.78) 8(11.805,8) 9(20.445,9.78) 10(21.465,8) 11(22.475,9.78) 12(23.495,8) 13(24.505,9.78) 14(25.525,8) 15(26.535,9.78) 16(27.555,8)
  silkscreen extent 0,0 32.3,15.85, body extent 0,0 32.3,15.85, height 13.46
THT_SWITCH_SPST_90 [mm]
  oval 2x1.2 hole 0.8: 1(-2.2,1.313) 2(2.2,1.313)
  oval 1.5x2.5 hole 0.8 slot 1.5 at 90 deg: 3(-3.486,-1.313) 4(3.486,-1.313)
  silkscreen extent -4.18,-2.81 4.18,3.74, body extent -4.18,-2.81 4.18,5.16, height 7.37

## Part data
C1 C2 C3 C4 C5 C6 C7 C8 C9 C10 C14 C15 C16 C17 C21 C22 C23 C25.1 C25.2 C25.3 C25.4 C25.5 C25.6 C25.7 C25.8 C26.1 C26.2 C26.3 C26.4 C26.5 C26.6 C26.7 C26.8 C27.1 C27.2 C27.3 C27.4 C27.5 C27.6 C27.7 C27.8 C28 C29 C31: library part Capacitor, "Capacitor"
C11 C12 C13 C18 C19 C20 C24.1 C24.2 C24.3 C24.4 C24.5 C24.6 C24.7 C24.8 C30: library part Capacitor_POL, "Capacitor_POL"
D1 D2 D10 D11 D16.1 D16.2 D16.3 D16.4 D16.5 D16.6 D16.7 D16.8 D17: library part Diode_Schottky, "Diode Schottky"
D3 D4 D5 D6 D7 D8 D9: library part Transil, "Transient Voltage Suppressor, Bidirectional"
D12.1 D12.2 D12.3 D12.4 D12.5 D12.6 D12.7 D12.8 D13.1 D13.2 D13.3 D13.4 D13.5 D13.6 D13.7 D13.8 D14.1 D14.2 D14.3 D14.4 D14.5 D14.6 D14.7 D14.8 D15.1 D15.2 D15.3 D15.4 D15.5 D15.6 D15.7 D15.8: library part Diode, "Diode_S1A+"
IC1.1 IC1.2 IC1.3 IC1.4 IC1.5 IC1.6 IC1.7 IC1.8: "optoèlen", Supplier Part Number 1=782-TCMT1109
L1 L2 L3 L4: library part Inductor, "Inductor"
LED1 LED3 LED4 LED5 LED6 LED7 LED8 LED9 LED10 LED11.1 LED11.2 LED11.3 LED11.4 LED11.5 LED11.6 LED11.7 LED11.8: library part LED, "LED"
LED2: library part LED_RGB, "LED RGB"
P1: library part RJ45_2PORT, "RJ45 - 2 port"
P2: library part Header_2x4_Trains_Project
P3 P4: library part Power_JACK_2.1/2.5, "Low Voltage Power Supply Connector"
P5 P6: library part Header_1x2
P7: library part Header_2x3, "Header 2x3"
Q1.1 Q1.2 Q1.3 Q1.4 Q1.5 Q1.6 Q1.7 Q1.8: library part Transistor_MOSFET_N, "Transistor MOSFET N"
Q2.1 Q2.2 Q2.3 Q2.4 Q2.5 Q2.6 Q2.7 Q2.8: "Transistor PNP"
R1 R2 R3 R4 R5 R7 R8 R9 R10 R11 R12 R13 R14 R15 R16 R17 R18 R19 R20 R21 R22 R23 R25.1 R25.2 R25.3 R25.4 R25.5 R25.6 R25.7 R25.8 R26.1 R26.2 R26.3 R26.4 R26.5 R26.6 R26.7 R26.8 R27.1 R27.2 R27.3 R27.4 R27.5 R27.6 R27.7 R27.8 R28.1 R28.2 R28.3 R28.4 R28.5 R28.6 R28.7 R28.8 R29.1 R29.2 R29.3 R29.4 R29.5 R29.6 R29.7 R29.8 R30.1 R30.2 R30.3 R30.4 R30.5 R30.6 R30.7 R30.8 R32 R32.1 R32.2 R32.3 R32.4 R32.5 R32.6 R32.7 R32.8 R33: library part Resistor, "Resistor"
R6: library part Resistor_PTC, "Resistor PTC"
R31.1 R31.2 R31.3 R31.4 R31.5 R31.6 R31.7 R31.8: library part Resistor_2512, "Resistor_2512"
S1 S2 S3 S4: library part HEX_SPACER_M3, "Hexagon metal spacer M3"
SW1 SW2: library part Switch_90, "Tactile Switch Right Angle"
U1: library part MC9S08DZ96, "NXP 8 Bit Microcontroller, CAN"
U2: "CAN Transceiver, 4.5 V - 5.5 V, 1 Mb/s"
U3: library part MCP2551, "CAN Transceiver, 4.5 V - 5.5 V, 1 Mb/s"
U4: "Buck (Step Down) Switching Regulator, 4.75V-40V Input, 5 V, 1A Output"
U5: library part TL2575-05, "Buck (Step Down) Switching Regulator, 4.75V-40V Input, 5 V, 1A Output"
U6.1 U6.2 U6.3 U6.4 U6.5 U6.6 U6.7 U6.8: "Current sense amplifiers are designed for costoptimized  applications."
U7: "Hradlo invertujici"
U8: "The MC34931EK is a monolithic H-bridge Power IC designed for any low voltage DC servo motor control application within the current and voltage limits stated in this specification."
Y1: library part XTAL, "Crystal Oscillator"

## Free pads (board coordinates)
  round 6 hole 3.2: ""(-33.274,-27.545)

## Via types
v1: diameter 1.27, hole 0.7, Top Layer to Bottom Layer, tented both sides, 115 vias
v2: diameter 6, hole 3.2, Top Layer to Bottom Layer, 4 vias
v3: diameter 4.05, hole 3.25, Top Layer to Bottom Layer, 2 vias

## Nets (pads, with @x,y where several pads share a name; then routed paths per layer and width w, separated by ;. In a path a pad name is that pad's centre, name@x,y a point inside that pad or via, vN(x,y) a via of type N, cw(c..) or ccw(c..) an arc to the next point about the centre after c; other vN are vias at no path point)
+5V: C1.1 C6.1 C7.1 C8.1 C13.1 C14.2 C15.2 C16.2 C26.1.2 C26.2.2 C26.3.2 C26.4.2 C26.5.2 C26.6.2 C26.7.2 C26.8.2 C28.2 D17.2 IC1.1.4 IC1.2.4 IC1.3.4 IC1.4.4 IC1.5.4 IC1.6.4 IC1.7.4 IC1.8.4 L1.1 L3.2 LED2.1 P7.1 R18.2 R19.2 R20.2 R32.2 U1.4 U1.30 U2.3 U3.3 U6.1.6 U6.2.6 U6.3.6 U6.4.6 U6.5.6 U6.6.6 U6.7.6 U6.8.6 U7.5 | length 459.9
  Top Layer w0.3: U7.5@-18.842,17.318 -18.842,16.81 -18.034,16.002 -14.097,16.002 ; 28.575,24.13 28.575,6.769 34.094,1.25 U1.4@35.9,1.25 ; U1.30@44.1,-0.25 48.933,-0.25 C6.1@50.448,1.265
  Top Layer w0.6: C26.8.2@-58.928,53.721 C26.8.2@-58.42,53.721 ; v1(-56.896,53.721) -55.857,53.721 U6.8.6@-55.306,53.17 ; C26.7.2@-43.307,53.848 -43.18,53.721 v1(-41.656,53.721) -40.617,53.721 U6.7.6@-40.066,53.17 ; C26.6.2@-28.067,53.848 -27.94,53.721 v1(-26.416,53.721) -25.377,53.721 U6.6.6@-24.826,53.17 ; C26.5.2@-12.827,53.848 -12.7,53.721 v1(-11.176,53.721) -10.137,53.721 U6.5.6@-9.586,53.17 ; C1.1@0.634,21.96 2.678,21.96 3.491,21.147 3.491,19.796 2.676,18.981 U2.3@1.829,18.981 ; C26.4.2@2.413,53.848 2.54,53.721 v1(4.064,53.721) 5.103,53.721 U6.4.6@5.654,53.17 ; C26.3.2@17.653,53.848 17.78,53.721 v1(19.304,53.721) 20.343,53.721 U6.3.6@20.894,53.17 ; 19.18,24.13 19.18,19.81 20.009,18.981 U3.3@20.72,18.981 ; C26.2.2@32.893,53.848 33.02,53.721 v1(34.544,53.721) 35.583,53.721 U6.2.6@36.134,53.17 ; L1.1@36.449,13.08 C8.1@38.981,13.08 C8.1@38.989,13.088 ; C26.1.2@48.244,53.72 v1(49.784,53.72) 51.054,53.72 51.374,53.4 U6.1.6@51.374,53.17 ; C6.1@50.448,1.265 52.436,1.265 C7.1@52.451,1.28 57.785,6.614 57.785,8.381 R20.2@60.325,10.921 ; 53.115,20.574 53.115,15.621 P7.1@54.385,14.351 55.471,13.265 R19.2@60.325,13.265 R20.2@60.325,10.921 ; IC1.1.4@53.115,25.257 IC1.1.4@53.115,25.329 ; LED2.1@63.615,-3.87 63.615,-3.568 67.564,0.381 67.564,5.842 64.515,8.891 62.355,8.891 R20.2@60.325,10.921
  Top Layer w1: C26.8.2@-58.928,53.721 -61.341,51.308 -61.341,26.416 -59.055,24.13 -53.569,24.13 ; C26.8.2@-58.42,53.721 v1(-56.896,53.721) ; IC1.8.4@-53.569,25.4 -53.569,24.13 ; C13.1@-45.635,8.255 -45.529,8.149 L3.2@-39.116,8.149 -33.575,8.149 C14.2@-33.528,8.102 C15.2@-31.75,8.102 C16.2@-29.951,8.102 -29.924,8.129 C28.2@-22.225,8.129 -21.081,8.129 -14.097,15.113 -14.097,16.002 -14.097,24.13 ; R18.2@-43.181,21.208 -41.676,21.208 D17.2@-41.056,21.828 -41.056,24.13 ; IC1.7.4@-38.33,25.4 -38.33,24.13 ; IC1.6.4@-23.09,25.4 -23.09,24.13 ; IC1.5.4@-7.849,25.4 -7.849,24.13 ; C1.1@0.634,21.96 0.634,24.13 ; IC1.4.4@7.392,25.4 7.392,24.13 ; IC1.3.4@22.633,25.4 22.633,24.13 ; L1.1@36.449,13.08 36.449,24.13 ; IC1.2.4@37.874,25.4 37.874,24.13 ; 53.115,20.574 53.115,24.13 ; IC1.1.4@53.115,25.257 53.115,24.13 ; IC1.1.4@53.115,25.329 IC1.1.4@53.115,25.4 ; -53.569,24.13 -41.056,24.13 ; -41.056,24.13 -38.33,24.13 ; -38.33,24.13 -23.09,24.13 ; -23.09,24.13 -14.097,24.13 ; -14.097,24.13 -7.849,24.13 ; -7.849,24.13 0.634,24.13 ; 0.634,24.13 7.392,24.13 ; 7.392,24.13 19.18,24.13 22.633,24.13 ; 22.633,24.13 28.575,24.13 36.449,24.13 ; 36.449,24.13 37.874,24.13 ; 37.874,24.13 53.115,24.13
  Bottom Layer w1: v1(49.784,53.72) 34.545,53.72 v1(34.544,53.721) 34.543,53.72 v1@19.305,53.72 ; v1@-56.895,53.72 -56.897,53.72 v1(-56.896,53.721) v1@-56.895,53.72 ; v1@-56.895,53.72 v1@-41.657,53.72 ; v1@-41.657,53.72 v1@-41.655,53.72 ; v1@-41.657,53.72 v1(-41.656,53.721) v1@-41.655,53.72 ; v1@-41.655,53.72 v1@-26.417,53.72 ; v1@-26.417,53.72 v1@-26.415,53.72 ; v1@-26.417,53.72 v1(-26.416,53.721) v1@-26.415,53.72 ; v1@-26.415,53.72 v1@-11.177,53.72 ; v1@-11.177,53.72 v1@-11.175,53.72 ; v1@-11.177,53.72 v1(-11.176,53.721) v1@-11.175,53.72 ; v1@-11.175,53.72 v1@4.063,53.72 ; v1@4.063,53.72 v1@4.065,53.72 ; v1@4.063,53.72 v1(4.064,53.721) v1@4.065,53.72 ; v1@4.065,53.72 v1@19.303,53.72 ; v1@19.303,53.72 v1@19.305,53.72 ; v1@19.303,53.72 v1(19.304,53.721) v1@19.305,53.72
+15V: C19.1 C20.1 C21.2 C22.2 C23.2 C29.1 C30.1 C31.2 L4.2 U5.4 U8.7 U8.8 U8.25 U8.26 | length 93.9
  Top Layer w1: C23.2@-63.985,-12.446 C22.2@-63.985,-10.287 ; -63.985,1.651 C21.2@-63.985,-8.255 C22.2@-63.985,-10.287 ; C19.1@-63.985,2.921 C19.1@-66.122,2.921 C20.1@-66.122,13.589 -64.135,13.589 -60.194,17.53 -49.28,17.53 -46.99,15.24 C30.1@-45.614,15.24 -40.006,15.24 C31.2@-40.005,15.239 -34.952,15.239 -34.951,15.24 ; L4.2@-60.833,-10.414 -57.912,-13.335 U5.4@-57.912,-17.526 ; L4.2@-60.833,-9.144 -60.833,-10.287 C22.2@-63.985,-10.287 ; -24.951,15.24 -24.95,15.241 C29.1@-22.218,15.241 -22.216,15.239 v1(-20.574,15.239)
  Bottom Layer w1: v1(-36.83,15.24) -36.829,15.239 v1(-20.574,15.239)
+24V: R1.1 R2.1 R3.2 R6.1 | length 76.3
  Top Layer w0.6: R2.1@1.27,10.794 1.969,10.095 5.145,10.095 14.986,0.254 14.986,-4.635 31.058,-20.707 R3.2@31.058,-26.67
  Top Layer w1: R6.1@-19.814,2.16 -11.879,10.095 -1.969,10.095 R1.1@-1.27,10.794 R2.1@1.27,10.794
+24V_ETH: D2.1 P1.3 P1.5 P1.11 P1.13 P2.3 P2.5 | length 78.7
  Top Layer w0.6: P1.5@-7.622,-22.604 P1.3@-9.652,-22.604 -10.796,-21.46 v1(-10.796,-10.16) -7.747,-10.16 -1.27,-3.683 P2.3@-1.27,-2.56 -1.27,-1.4 -2.541,-0.129 -2.541,5.969 D2.1@-2.152,5.969 ; P2.5@1.27,-1.524 P2.5@1.27,-2.56 1.27,-3.629 5.08,-7.439 v1(5.08,-10.17) 5.08,-21.586 P1.11@6.098,-22.604 P1.13@8.128,-22.604
  Bottom Layer w0.6: v1(-10.796,-10.16) 5.07,-10.16 v1(5.08,-10.17)
+24V_JACK: D1.1 P3.1 P4.1 | length 150.1
  Top Layer w1: D1.1@-21.59,-11.294 -21.59,-18.042 -22.694,-19.146 P3.1@-24.003,-19.146 -25.242,-19.146 -27.559,-21.463 -27.559,-27.535 -24.614,-30.48 15.751,-30.48 19.424,-26.807 19.424,-21.343 21.59,-19.177 P4.1@22.987,-19.177
  Bottom Layer w1: P3.1@-24.003,-19.146 -25.242,-19.146 -27.559,-21.463 -27.559,-27.559 -24.638,-30.48 15.749,-30.48 19.431,-26.798 19.431,-21.336 21.59,-19.177 P4.1@22.987,-19.177
BKGD: P7.6 U1.33 | length 22.4
  Top Layer w0.3: U1.33@44.1,1.25 45.827,1.25 50.419,5.842 50.419,18.005 P7.6@51.845,19.431
CAN_H: D4.1 D5.2 P1.1 P1.9 P2.1 R4.2 U2.7 | length 78.5
  Top Layer w0.6: P1.1@-12.063,-22.604 v1(-12.063,-8.9) -12.063,-7.744 R4.2@-8.129,-3.81 -6.859,-2.54 v1(-6.35,-2.54) -3.83,-2.54 P2.1@-3.81,-2.56 ; v1(-6.35,11.43) -6.35,13.4 -6.065,13.685 -5.969,13.589 D5.2@-5.969,16.68 -5.969,17.384 -5.642,17.711 U2.7@-2.851,17.711 ; v1(3.81,-8.9) 3.81,-22.346 P1.9@4.068,-22.604
  Bottom Layer w0.6: v1(-12.063,-8.9) v1(3.81,-8.9) ; v1(-6.35,-2.54) v1(-6.35,11.43)
CAN_L: D3.1 D4.2 P1.2 P1.10 P2.2 P5.2 U2.6 | length 94.1
  Top Layer w0.6: P1.2@-10.662,-24.384 -12.065,-24.384 -13.335,-23.114 v1(-13.335,-7.63) -13.335,-1.779 P5.2@-10.223,1.333 ; P5.2@-10.16,1.27 -8.89,2.54 P2.2@-3.81,2.54 ; v1(-8.89,11.43) -8.89,13.518 -9.271,13.899 D3.1@-9.271,16.68 -9.271,16.775 -9.45,16.954 -7.424,18.981 U2.6@-2.851,18.981 ; v1(2.541,-7.63) 2.541,-23.115 3.81,-24.384 P1.10@5.088,-24.384
  Bottom Layer w0.6: v1(-13.335,-7.63) v1(2.541,-7.63) ; P5.2@-10.16,1.27 -8.89,2.54 v1(-8.89,11.43)
CAN_RX: U1.22 U2.4 | length 64.8
  Top Layer w0.3: U1.22@41.75,-4.1 41.75,-5.427 43.053,-6.73 v1(43.053,-8.238)
  Top Layer w0.6: v1(0,13.462) 0,19.305 0.946,20.251 U2.4@1.829,20.251
  Bottom Layer w0.6: v1(0,13.462) 0.127,13.335 11.684,13.335 33.274,-8.255 33.291,-8.238 v1(43.053,-8.238)
CAN_TX: U1.21 U2.1 | length 54
  Top Layer w0.3: U1.21@41.25,-4.1 41.25,-6.325 v1(41.91,-6.985)
  Top Layer w0.6: v1(1.959,14.478) U2.1@1.959,16.441
  Bottom Layer w0.6: v1(1.959,14.478) 11.781,14.478 33.244,-6.985 v1(41.91,-6.985)
DCC+: D8.1 D9.2 P1.7 P1.15 P2.7 R5.2 U3.7 | length 89.3
  Top Layer w0.6: P1.7@-5.592,-22.604 -5.08,-22.092 v1(-5.08,-11.43) ; P2.7@3.81,-2.56 3.83,-2.54 v1(6.35,-2.54) 6.863,-2.54 R5.2@8.133,-3.81 10.795,-6.472 v1(10.795,-11.43) 10.795,-21.967 P1.15@10.158,-22.604 ; D8.1@5.978,14.28 D9.2@5.978,16.68 5.978,17.154 7.979,19.155 10.615,19.155 13.177,21.717 17.018,21.717 17.526,21.209 17.526,18.413 16.824,17.711 U3.7@16.339,17.711 ; v1(6.35,11.43) D8.1@6.35,13.685
  Bottom Layer w0.6: v1(-5.08,-11.43) v1(10.795,-11.43) ; v1(6.35,-2.54) v1(6.35,11.43)
DCC-: D7.1 D8.2 P1.8 P1.16 P2.8 P6.2 U3.6 | length 84.6
  Top Layer w0.6: P1.8@-4.572,-24.384 -3.81,-23.622 v1(-3.81,-12.7) ; P2.8@3.81,2.54 8.89,2.54 P6.2@10.16,1.27 12.065,-0.635 v1(12.065,-12.7) 12.065,-23.497 P1.16@11.178,-24.384 ; v1(8.89,11.43) D8.2@8.89,13.716 ; D8.2@9.271,13.955 D7.1@9.271,16.68 11.572,18.981 U3.6@15.693,18.981
  Bottom Layer w0.6: v1(-3.81,-12.7) v1(12.065,-12.7) ; v1(8.89,11.43) 8.89,2.54 P6.2@10.16,1.27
